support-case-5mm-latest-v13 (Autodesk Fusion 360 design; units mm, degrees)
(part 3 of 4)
offset_faces "OffsetFaces9" distance -0.2
offset_faces "OffsetFaces10" distance -0.2
sketch "Sketch42" plane through (87.9, 0, 0) normal (-1, 0, 0) x axis (0, -1, 0)
  line L1 (-42.6941, 1.4134) -> (-39.025, 1.4134)
  line L2 (-39.025, 5.5134) -> (-42.6941, 5.5134)
  line L3 (-36.6258, -0.6871) -> (-36.1258, 0.3129)
  line L4 (-36.8742, 0.6871) -> (-37.3742, -0.3129)
  line L5 (-42.0276, 9.5417) -> (-40.8255, 7.1376)
  line L6 (-38.6336, 8.2336) -> (-39.8356, 10.6377)
  line L7 (-44.3847, -0.2206) -> (-43.6433, -1.2821)
  line L8 (-42.503, -0.4857) -> (-43.2444, 0.5758)
  line L9 (-39.809, -1.2436) -> (-38.3992, -0.0011)
  line L10 (-39.1812, 0.8862) -> (-40.591, -0.3564)
  line L11 (-32.6474, 3.0718) -> (-31.5271, 3.9384)
  line L12 (-32.7999, 5.5837) -> (-33.9202, 4.7171)
  line L13 (-47.0891, -0.5864) -> (-45.9587, 2.459)
  line L14 (-47.497, 3.03) -> (-48.6275, -0.0154)
  curve K1 (-49.7958, -1.519) -> (-53.502, -1.4707)
  line L15 (-34.6, -1.519) -> (-42.7898, -1.519)
  line L16 (-34.6, 0.4) -> (-34.6, -1.519)
  line L17 (-20.9875, 1.4) -> (-33.6, 1.4)
  line L18 (-19.9875, -1.519) -> (-19.9875, 0.4)
  line L19 (-6.2042, -1.519) -> (-19.9875, -1.519)
  curve K2 (-2.4862, -1.4711) -> (-6.2042, -1.519)
  line L20 (-2.4862, 23.1) -> (-2.4862, -1.4711)
  line L21 (-14.0576, 23.1) -> (-2.4862, 23.1)
  line L22 (-39.9941, 21.6) -> (-15.9941, 21.6)
  line L23 (-53.502, 23.1) -> (-41.9306, 23.1)
  line L24 (-53.502, -1.4707) -> (-53.502, 23.1)
  line L25 (-34.7657, 6.2918) -> (-37.5941, 3.4634)
  line L26 (-33.5941, 3.4634) -> (-37.5941, 3.4634)
  line L27 (-45.169, 0.9885) -> (-42.6941, 3.4634)
  line L28 (-39.1941, 3.4634) -> (-42.6941, 3.4634)
  line L29 (-45.169, 2.0492) -> (-43.7548, 3.4634)
  line L30 (-42.6941, 2.4027) -> (-44.1083, 0.9885)
  line L31 (-45.169, 0.9885) -> (-42.6941, 3.4634)
  line L32 (-34.7657, 5.2312) -> (-36.5335, 3.4634)
  line L33 (-37.5941, 4.5241) -> (-35.8264, 6.2918)
  line L34 (-34.7657, 6.2918) -> (-37.5941, 3.4634)
  line L35 (-43.3565, -1.519) -> (-49.7958, -1.519)
  arc A1 centre (-37.5941, 3.4634) radius 2.5 clockwise from (-39.025, 5.5134) to (-39.025, 1.4134)
  arc A2 centre (-42.6941, 3.4634) radius 2.05 clockwise from (-42.6941, 1.4134) to (-42.6941, 5.5134)
  arc A3 centre (-37, -0.5) radius 0.4184 clockwise from (-36.6258, -0.6871) to (-37.3742, -0.3129)
  arc A4 centre (-36.5, 0.5) radius 0.4184 clockwise from (-36.8742, 0.6871) to (-36.1258, 0.3129)
  arc A5 centre (-40.9316, 10.0897) radius 1.2254 clockwise from (-42.0276, 9.5417) to (-39.8356, 10.6377)
  arc A6 centre (-39.7296, 7.6856) radius 1.2254 clockwise from (-38.6336, 8.2336) to (-40.8255, 7.1376)
  arc A7 centre (-43.8145, 0.1776) radius 0.6955 clockwise from (-44.3847, -0.2206) to (-43.2444, 0.5758)
  arc A8 centre (-43.0731, -0.8839) radius 0.6955 clockwise from (-42.503, -0.4857) to (-42.7898, -1.519)
  arc A9 centre (-40.2, -0.8) radius 0.5914 clockwise from (-39.809, -1.2436) to (-40.591, -0.3564)
  arc A10 centre (-38.7902, 0.4426) radius 0.5914 clockwise from (-39.1812, 0.8862) to (-38.3992, -0.0011)
  arc A11 centre (-33.2838, 3.8945) radius 1.0401 clockwise from (-32.6474, 3.0718) to (-33.9202, 4.7171)
  arc A12 centre (-32.1635, 4.7611) radius 1.0401 clockwise from (-32.7999, 5.5837) to (-31.5271, 3.9384)
  arc A13 centre (-47.8583, -0.3009) radius 0.8205 clockwise from (-47.0891, -0.5864) to (-48.6275, -0.0154)
  arc A14 centre (-46.7279, 2.7445) radius 0.8205 clockwise from (-47.497, 3.03) to (-45.9587, 2.459)
  arc A15 centre (-33.6, 0.4) radius 1 clockwise from (-34.6, 0.4) to (-33.6, 1.4)
  arc A16 centre (-20.9875, 0.4) radius 1 clockwise from (-20.9875, 1.4) to (-19.9875, 0.4)
  arc A17 centre (-14.0576, 22.6) radius 0.5 clockwise from (-14.5418, 22.725) to (-14.0576, 23.1)
  arc A18 centre (-15.9941, 23.1) radius 1.5 clockwise from (-14.5418, 22.725) to (-15.9941, 21.6)
  arc A19 centre (-39.9941, 23.1) radius 1.5 clockwise from (-39.9941, 21.6) to (-41.4465, 22.725)
  arc A20 centre (-41.9306, 22.6) radius 0.5 clockwise from (-41.9306, 23.1) to (-41.4465, 22.725)
  arc A21 centre (-44.6387, 1.5188) radius 0.75 clockwise from (-44.1083, 0.9885) to (-45.169, 2.0492)
  arc A22 centre (-43.2245, 2.9331) radius 0.75 clockwise from (-43.7548, 3.4634) to (-42.6941, 2.4027)
  arc A23 centre (-35.296, 5.7615) radius 0.75 clockwise from (-35.8264, 6.2918) to (-34.7657, 5.2312)
  arc A24 centre (-37.0638, 3.9937) radius 0.75 clockwise from (-36.5335, 3.4634) to (-37.5941, 4.5241)
  arc A25 centre (-43.0731, -0.8839) radius 0.6955 clockwise from (-43.3565, -1.519) to (-43.6433, -1.2821)
  point P4 (-37.5941, 3.4634)
  point P70 (-37.5941, 3.4634)
  point P7 (-42.6941, 3.4634)
  point P73 (-42.6941, 3.4634)
  point P82 (-42.6941, 3.4634)
  point P74 (-45.169, 0.9885)
  point P89 (-37.5941, 3.4634)
  point P71 (-34.7657, 6.2918)
  horizontal L26
  coincident P4 P70
  horizontal L28
  coincident P7 P73
  tangent L29 A21
  tangent A21 L30
  parallel L29 L30
  tangent L30 A22
  tangent L29 A22
  midpoint A22 P82
  midpoint P74 A21
  parallel L27 L31
  coincident P7 P82
  tangent L32 A23
  tangent A23 L33
  parallel L32 L33
  tangent L33 A24
  tangent L32 A24
  midpoint A24 P89
  midpoint P71 A23
  parallel L25 L34
  coincident P4 P89
  dimension "d352" distance P70 P71 = 4
  dimension "d353" angle L25 L26 = 45
  dimension "d354" angle L27 L28 = 135
  dimension "d355" distance P73 P74 = 3.5
  dimension "d356" diameter A21 = 1.5
  dimension "d357" diameter A23 = 1.5
extrude "Extrude56" cut sketch "Sketch42" profile of A1 A2 L25 L27 L29 A21 L30 L32 A23 L33 against normal blind 2
extrude "Extrude57" add sketch "Sketch42" profile of A1 A2 L25 L27 L29 A21 L30 A22 L32 A23 L33 A24 against normal blind 2
sketch "Sketch43" plane through (90.7, 0, 0) normal (1, 0, 0) x axis (0, 1, 0)
  line L1 (37.5941, 5.3134) -> (41.9463, 5.3134)
  line L2 (41.9463, 1.6134) -> (37.5941, 1.6134)
  line L3 (43.7963, 3.4634) -> (35.7441, 3.4634)
  line L4 (40, 4.9702) -> (40, 3.6932)
  line L5 (39.5405, 3.6932) -> (39.5405, 4.9702)
  line L6 (39.7702, 5.2) -> (39.7702, 3.4634)
  line L7 (39.2702, 4.9702) -> (39.7702, 4.9702)
  line L8 (40.2702, 4.9702) -> (39.7702, 4.9702)
  line L9 (39.2702, 4.3294) -> (39.2702, 4.9702)
  line L10 (40.2702, 4.3294) -> (40.2702, 4.9702)
  arc A1 centre (41.9463, 3.4634) radius 1.85 clockwise from (41.9463, 5.3134) to (41.9463, 1.6134)
  arc A2 centre (37.5941, 3.4634) radius 1.85 clockwise from (37.5941, 1.6134) to (37.5941, 5.3134)
  circle C1 centre (39.7702, 3.4634) radius 1
  circle C2 centre (39.7702, 3.4634) radius 1.5
  arc A3 centre (39.7702, 4.9702) radius 0.2298 clockwise from (39.5405, 4.9702) to (40, 4.9702)
  arc A4 centre (39.7702, 3.6932) radius 0.2298 clockwise from (40, 3.6932) to (39.5405, 3.6932)
  point P8 (35.7441, 3.4634)
  point P9 (43.7963, 3.4634)
  point P10 (39.7702, 3.4634)
  point P18 (39.7702, 3.4634)
  point P19 (39.7702, 5.2)
  point P17 (39.7702, 4.9702)
  point P20 (39.7702, 4.9702)
  point P22 (39.7702, 4.9702)
  point P24 (39.2702, 4.3294)
  point P25 (40.2702, 4.3294)
  point P21 (39.2702, 4.9702)
  point P23 (40.2702, 4.9702)
  midpoint A2 P8
  midpoint A1 P9
  midpoint L3 P10
  tangent L4 A3
  tangent A3 L5
  parallel L4 L5
  tangent L5 A4
  tangent L4 A4
  midpoint A4 P18
  midpoint A3 P19
  perpendicular L3 L6
  coincident P10 P18
  coincident P17 P20
  perpendicular L6 L7
  coincident P17 P22
  perpendicular L6 L8
  coincident C1 P24
  perpendicular L7 L9
  coincident C1 P25
  perpendicular L8 L10
  dimension "d362" diameter C1 = 2
  dimension "d363" = 0.5
  dimension "d364" distance P20 P21 = 0.5
  dimension "d365" distance P22 P23 = 0.5
extrude "Extrude58" cut sketch "Sketch43" profile of L3 C1 C2 L4 A3 L5 A4 L7 L8 L9 L10 against normal blind 0.5
offset_faces "OffsetFaces11" distance -0.1
offset_faces "OffsetFaces12" distance -0.1
extrude "Extrude59" add of existing geometry blind 0.5
delete_face "DeleteFace75"
delete_face "DeleteFace76"
offset_faces "OffsetFaces13" distance 0.1
move_face "MoveFace6"
move_face "MoveFace7"
move_face "MoveFace8"
extrude "Extrude60" add of existing geometry blind 3.9 second side blind -0.2
split "Split1"
extrude "Extrude61" cut of existing geometry blind -0.4
sketch "Sketch44" plane through (0, 0, 1.6134) normal (0, 0, -1) x axis (1, 0, 0)
  line L1 (89.669, -41.4517) -> (90.45, -41.4517)
  line L2 (90.45, -41.9517) -> (89.669, -41.9517)
  line L3 (89.419, -41.7017) -> (90.7, -41.7017)
  line L4 (89.75, -37.5941) -> (90.45, -37.5941)
  line L5 (90.45, -38.0941) -> (89.75, -38.0941)
  line L6 (89.5, -37.8441) -> (90.7, -37.8441)
  line L7 (89.75, -38.9116) -> (90.45, -38.9116)
  line L8 (90.45, -39.4116) -> (89.75, -39.4116)
  line L9 (89.5, -39.1616) -> (90.7, -39.1616)
  line L10 (89.75, -40.3058) -> (90.45, -40.3058)
  line L11 (90.45, -40.8058) -> (89.75, -40.8058)
  line L12 (89.5, -40.5558) -> (90.7, -40.5558)
  line L13 (88.0999, -42.1845) -> (88.9142, -42.1845)
  line L14 (88.9142, -42.6845) -> (88.0999, -42.6845)
  line L15 (87.8499, -42.4345) -> (89.1642, -42.4345)
  line L16 (88.0672, -39.0366) -> (88.9256, -39.0366)
  line L17 (88.9256, -39.5366) -> (88.0672, -39.5366)
  line L18 (87.8172, -39.2866) -> (89.1756, -39.2866)
  line L19 (88.0572, -41.3428) -> (88.9428, -41.3428)
  line L20 (88.9428, -41.8428) -> (88.0572, -41.8428)
  line L21 (87.8072, -41.5928) -> (89.1928, -41.5928)
  line L22 (88.0771, -40.3229) -> (88.9229, -40.3229)
  line L23 (88.9229, -40.8229) -> (88.0771, -40.8229)
  line L24 (87.8271, -40.5729) -> (89.1729, -40.5729)
  line L25 (89.5, -41.9463) -> (89.5, -37.5941)
  line L26 (90.7, -37.5941) -> (90.7, -41.9463)
  line L27 (90.7, -41.9463) -> (89.5, -41.9463)
  line L28 (89.5, -37.5941) -> (90.7, -37.5941)
  arc A1 centre (89.669, -41.7017) radius 0.25 clockwise from (89.669, -41.9517) to (89.669, -41.4517)
  arc A2 centre (90.45, -41.7017) radius 0.25 clockwise from (90.45, -41.4517) to (90.45, -41.9517)
  arc A3 centre (89.75, -37.8441) radius 0.25 clockwise from (89.75, -38.0941) to (89.75, -37.5941)
  arc A4 centre (90.45, -37.8441) radius 0.25 clockwise from (90.45, -37.5941) to (90.45, -38.0941)
  arc A5 centre (89.75, -39.1616) radius 0.25 clockwise from (89.75, -39.4116) to (89.75, -38.9116)
  arc A6 centre (90.45, -39.1616) radius 0.25 clockwise from (90.45, -38.9116) to (90.45, -39.4116)
  arc A7 centre (89.75, -40.5558) radius 0.25 clockwise from (89.75, -40.8058) to (89.75, -40.3058)
  arc A8 centre (90.45, -40.5558) radius 0.25 clockwise from (90.45, -40.3058) to (90.45, -40.8058)
  arc A9 centre (88.0999, -42.4345) radius 0.25 clockwise from (88.0999, -42.6845) to (88.0999, -42.1845)
  arc A10 centre (88.9142, -42.4345) radius 0.25 clockwise from (88.9142, -42.1845) to (88.9142, -42.6845)
  arc A11 centre (88.0672, -39.2866) radius 0.25 clockwise from (88.0672, -39.5366) to (88.0672, -39.0366)
  arc A12 centre (88.9256, -39.2866) radius 0.25 clockwise from (88.9256, -39.0366) to (88.9256, -39.5366)
  arc A13 centre (88.0572, -41.5928) radius 0.25 clockwise from (88.0572, -41.8428) to (88.0572, -41.3428)
  arc A14 centre (88.9428, -41.5928) radius 0.25 clockwise from (88.9428, -41.3428) to (88.9428, -41.8428)
  arc A15 centre (88.0771, -40.5729) radius 0.25 clockwise from (88.0771, -40.8229) to (88.0771, -40.3229)
  arc A16 centre (88.9229, -40.5729) radius 0.25 clockwise from (88.9229, -40.3229) to (88.9229, -40.8229)
  point P8 (90.7, -41.7017)
  point P9 (89.419, -41.7017)
  point P16 (90.7, -37.8441)
  point P17 (89.5, -37.8441)
  point P24 (90.7, -39.1616)
  point P25 (89.5, -39.1616)
  point P32 (90.7, -40.5558)
  point P33 (89.5, -40.5558)
  point P40 (89.1642, -42.4345)
  point P41 (87.8499, -42.4345)
  point P48 (89.1756, -39.2866)
  point P49 (87.8172, -39.2866)
  point P56 (89.1928, -41.5928)
  point P57 (87.8072, -41.5928)
  point P64 (89.1729, -40.5729)
  point P65 (87.8271, -40.5729)
  tangent L1 A1
  tangent A1 L2
  parallel L1 L2
  tangent L2 A2
  tangent L1 A2
  midpoint A2 P8
  midpoint A1 P9
  tangent L4 A3
  tangent A3 L5
  parallel L4 L5
  tangent L5 A4
  tangent L4 A4
  midpoint A4 P16
  midpoint A3 P17
  tangent L7 A5
  tangent A5 L8
  parallel L7 L8
  tangent L8 A6
  tangent L7 A6
  midpoint A6 P24
  midpoint A5 P25
  tangent L10 A7
  tangent A7 L11
  parallel L10 L11
  tangent L11 A8
  tangent L10 A8
  midpoint A8 P32
  midpoint A7 P33
  tangent L13 A9
  tangent A9 L14
  parallel L13 L14
  tangent L14 A10
  tangent L13 A10
  midpoint A10 P40
  midpoint A9 P41
  horizontal L15
  tangent L16 A11
  tangent A11 L17
  parallel L16 L17
  tangent L17 A12
  tangent L16 A12
  midpoint A12 P48
  midpoint A11 P49
  horizontal L18
  tangent L19 A13
  tangent A13 L20
  parallel L19 L20
  tangent L20 A14
  tangent L19 A14
  midpoint A14 P56
  midpoint A13 P57
  horizontal L21
  tangent L22 A15
  tangent A15 L23
  parallel L22 L23
  tangent L23 A16
  tangent L22 A16
  midpoint A16 P64
  midpoint A15 P65
  horizontal L24
  dimension "d405" distance L7 L8 = 0.5
  dimension "d406" distance L4 L5 = 0.5
  dimension "d407" distance L10 L11 = 0.5
  dimension "d408" distance L1 L2 = 0.5
  dimension "d409" distance L13 L14 = 0.5
  dimension "d410" distance L19 L20 = 0.5
  dimension "d411" distance L22 L23 = 0.5
  dimension "d412" distance L16 L17 = 0.5
extrude "Extrude62" add sketch "Sketch44" profile of L1 A1 L2 A2 L4 A3 L5 A4 L7 A5 L8 A6 L10 A7 L11 A8 L13 A9 L14 A10 L16 A11 L17 A12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 along normal blind 0.2
sketch "Sketch45" plane through (0, 41.9517, 0) normal (0, 1, 0) x axis (-1, 0, 0)
  line L1 (-89.9364, 1.4134) -> (-89.9364, 5.3134)
  line L2 (-90.2657, 1.4134) -> (-89.9364, 1.4134)
  line L3 (-90.2657, 5.3134) -> (-90.2657, 1.4134)
  line L4 (-90.2657, 4.3984) -> (-89.9364, 4.3984)
  line L5 (-90.7, 5.3134) -> (-89.5, 5.3134)
  line L6 (-89.5, 5.3134) -> (-89.5, 1.6134)
  line L7 (-90.5016, 1.6134) -> (-90.7, 1.6134)
  line L8 (-89.6174, 1.6134) -> (-90.5016, 1.6134)
  line L9 (-90.7, 1.6134) -> (-90.7, 5.3134)
  line L10 (-89.5, 1.6134) -> (-89.6174, 1.6134)
  point P6 (-89.9364, 4.3984)
  point P7 (-90.2657, 4.3984)
  vertical L1
  horizontal L2
  vertical L3
  coincident L1 P6
  coincident L3 P7
  perpendicular L3 L4
extrude "Extrude63" cut sketch "Sketch45" profile of L1 L2 L3 L4 against normal blind 4.353
sketch "Sketch46" plane through (0, 42.6941, 0) normal (0, 1, 0) x axis (-1, 0, 0)
  line L1 (-89.1, 1.6134) -> (-89.1, 5.3134)
  line L2 (-87.9, 1.6134) -> (-89.1, 1.6134)
  line L3 (-87.9, 5.3134) -> (-87.9, 1.6134)
  line L4 (-89.1, 5.3134) -> (-87.9, 5.3134)
  line L5 (-88.3, 5.3134) -> (-88.7263, 5.3134)
  line L6 (-88.3, 1.4) -> (-88.3, 5.3134)
  line L7 (-88.7263, 1.4) -> (-88.3, 1.4)
  line L8 (-88.7263, 5.3134) -> (-88.7263, 1.4)
  line L9 (-88.3, 4.4724) -> (-88.7263, 4.4724)
  point P6 (-88.7263, 5.3134)
  point P10 (-88.7263, 4.4724)
  point P11 (-88.3, 4.4724)
  horizontal L5
  vertical L6
  horizontal L7
  vertical L8
  coincident L4 P6
  coincident L8 P10
  coincident L6 P11
  perpendicular L6 L9
extrude "Extrude64" cut sketch "Sketch46" profile of L2 L6 L8 L9 against normal blind 3.7
extrude "Extrude65" cut of existing geometry blind -0.2
delete_face "DeleteFace77"
delete_face "DeleteFace78"
delete_face "DeleteFace79"
sketch "Sketch52" plane through (0, 0, -1.519) normal (0, 0, 1) x axis (-1, 0, 0)
  curve K1 (-9.9047, -21.9534) -> (-9.8441, -21.9301)
  line L1 (-10.1191, -21.9534) -> (-9.9047, -21.9534)
  curve K2 (-10.8368, -21.6668) -> (-10.1191, -21.9534)
  curve K3 (-11.1351, -20.9794) -> (-10.8368, -21.6668)
  curve K4 (-10.8368, -20.2919) -> (-11.1351, -20.9794)
  curve K5 (-10.1191, -20.0053) -> (-10.8368, -20.2919)
  line L2 (-9.9187, -20.0053) -> (-10.1191, -20.0053)
  curve K6 (-9.8605, -20.0286) -> (-9.9187, -20.0053)
  curve K7 (-9.8348, -20.0892) -> (-9.8605, -20.0286)
  line L3 (-9.8348, -20.4947) -> (-9.8348, -20.0892)
  curve K8 (-9.8908, -20.5506) -> (-9.8348, -20.4947)
  line L4 (-10.1191, -20.5506) -> (-9.8908, -20.5506)
  curve K9 (-10.4547, -20.6764) -> (-10.1191, -20.5506)
  curve K10 (-10.5945, -20.9794) -> (-10.4547, -20.6764)
  curve K11 (-10.4547, -21.2776) -> (-10.5945, -20.9794)
  curve K12 (-10.1191, -21.4035) -> (-10.4547, -21.2776)
  line L5 (-9.8768, -21.4035) -> (-10.1191, -21.4035)
  curve K13 (-9.8208, -21.4641) -> (-9.8768, -21.4035)
  line L6 (-9.8208, -21.8695) -> (-9.8208, -21.4641)
  curve K14 (-9.8441, -21.9301) -> (-9.8208, -21.8695)
  curve K15 (-14.5107, -18.5559) -> (-14.5176, -18.6305)
  curve K16 (-14.4384, -18.5186) -> (-14.5107, -18.5559)
  line L7 (-13.9957, -18.5186) -> (-14.4384, -18.5186)
  curve K17 (-13.9491, -18.5466) -> (-13.9957, -18.5186)
  line L8 (-13.2919, -20.2011) -> (-13.9491, -18.5466)
  curve K18 (-13.2873, -20.243) -> (-13.2919, -20.2011)
  line L9 (-13.2873, -20.6764) -> (-13.2873, -20.243)
  curve K19 (-13.3432, -20.7324) -> (-13.2873, -20.6764)
  line L10 (-13.4504, -20.7324) -> (-13.3432, -20.7324)
  curve K20 (-13.7953, -20.8256) -> (-13.4504, -20.7324)
  curve K21 (-13.9304, -21.0866) -> (-13.7953, -20.8256)
  curve K22 (-13.7929, -21.3615) -> (-13.9304, -21.0866)
  curve K23 (-13.4504, -21.4641) -> (-13.7929, -21.3615)
  line L11 (-13.2127, -21.4641) -> (-13.4504, -21.4641)
  curve K24 (-13.1521, -21.5246) -> (-13.2127, -21.4641)
  line L12 (-13.1521, -21.9254) -> (-13.1521, -21.5246)
  curve K25 (-13.1778, -21.9884) -> (-13.1521, -21.9254)
  curve K26 (-13.2407, -22.014) -> (-13.1778, -21.9884)
  line L13 (-13.4504, -22.014) -> (-13.2407, -22.014)
  curve K27 (-14.1751, -21.7483) -> (-13.4504, -22.014)
  curve K28 (-14.471, -21.0866) -> (-14.1751, -21.7483)
  curve K29 (-14.3196, -20.5972) -> (-14.471, -21.0866)
  curve K30 (-13.9164, -20.2756) -> (-14.3196, -20.5972)
  curve K31 (-13.8838, -20.2011) -> (-13.9164, -20.2756)
  line L14 (-14.5176, -18.6305) -> (-13.8838, -20.2011)
  curve K32 (-16.8926, -18.5979) -> (-16.9159, -18.5373)
  line L15 (-16.8926, -20.3036) -> (-16.8926, -18.5979)
  curve K33 (-16.9136, -20.3409) -> (-16.8926, -20.3036)
  curve K34 (-16.9579, -20.3455) -> (-16.9136, -20.3409)
  curve K35 (-17.3354, -19.9611) -> (-16.9579, -20.3455)
  curve K36 (-17.4938, -19.3482) -> (-17.3354, -19.9611)
  line L16 (-17.4938, -18.5979) -> (-17.4938, -19.3482)
  curve K37 (-17.4682, -18.5373) -> (-17.4938, -18.5979)
  curve K38 (-17.4099, -18.514) -> (-17.4682, -18.5373)
  line L17 (-16.9765, -18.514) -> (-17.4099, -18.514)
  curve K39 (-16.9159, -18.5373) -> (-16.9765, -18.514)
  curve K40 (-16.8926, -21.0633) -> (-16.9229, -20.984)
  line L18 (-16.8926, -21.8835) -> (-16.8926, -21.0633)
  curve K41 (-16.9299, -21.9674) -> (-16.8926, -21.8835)
  curve K42 (-17.0138, -21.9953) -> (-16.9299, -21.9674)
  line L19 (-17.4332, -21.9674) -> (-17.0138, -21.9953)
  curve K43 (-17.5824, -21.8695) -> (-17.4332, -21.9674)
  curve K44 (-18.6869, -19.8096) -> (-17.5824, -21.8695)
  curve K45 (-19.1623, -19.4834) -> (-18.6869, -19.8096)
  line L20 (-19.2741, -19.4834) -> (-19.1623, -19.4834)
  curve K46 (-19.344, -19.4135) -> (-19.2741, -19.4834)
  line L21 (-19.344, -18.5839) -> (-19.344, -19.4135)
  curve K47 (-19.323, -18.535) -> (-19.344, -18.5839)
  curve K48 (-19.2741, -18.514) -> (-19.323, -18.535)
  line L22 (-18.8453, -18.514) -> (-19.2741, -18.514)
  curve K49 (-18.6915, -18.6072) -> (-18.8453, -18.514)
  curve K50 (-18.3513, -19.2387) -> (-18.6915, -18.6072)
  curve K51 (-17.8666, -20.1405) -> (-18.3513, -19.2387)
  curve K52 (-17.601, -20.6298) -> (-17.8666, -20.1405)
  curve K53 (-17.4216, -20.8465) -> (-17.601, -20.6298)
  curve K54 (-17.1909, -20.9281) -> (-17.4216, -20.8465)
  curve K55 (-17.1186, -20.9351) -> (-17.1909, -20.9281)
  curve K56 (-17.0487, -20.9421) -> (-17.1186, -20.9351)
  curve K57 (-16.9998, -20.9467) -> (-17.0487, -20.9421)
  curve K58 (-16.9229, -20.984) -> (-16.9998, -20.9467)
  curve K59 (-22.7825, -21.9348) -> (-22.7615, -21.9884)
  line L23 (-22.7825, -21.478) -> (-22.7825, -21.9348)
  curve K60 (-22.7615, -21.4291) -> (-22.7825, -21.478)
  curve K61 (-22.7126, -21.4081) -> (-22.7615, -21.4291)
  line L24 (-20.2985, -21.4081) -> (-22.7126, -21.4081)
  curve K62 (-20.2286, -21.478) -> (-20.2985, -21.4081)
  line L25 (-20.2286, -21.9348) -> (-20.2286, -21.478)
  curve K63 (-20.2985, -22.0093) -> (-20.2286, -21.9348)
  line L26 (-22.7126, -22.0093) -> (-20.2985, -22.0093)
  curve K64 (-22.7615, -21.9884) -> (-22.7126, -22.0093)
  line L27 (-24.5665, -21.9534) -> (-24.4081, -21.3196)
  curve K65 (-24.6504, -22.014) -> (-24.5665, -21.9534)
  line L28 (-25.1211, -22.014) -> (-24.6504, -22.014)
  curve K66 (-25.2003, -21.9534) -> (-25.1211, -22.014)
  line L29 (-26.0998, -18.6212) -> (-25.2003, -21.9534)
  curve K67 (-26.0858, -18.5466) -> (-26.0998, -18.6212)
  curve K68 (-26.0206, -18.514) -> (-26.0858, -18.5466)
  line L30 (-25.5918, -18.514) -> (-26.0206, -18.514)
  curve K69 (-25.5126, -18.5746) -> (-25.5918, -18.514)
  line L31 (-24.8461, -20.9887) -> (-25.5126, -18.5746)
  curve K70 (-24.7436, -21.1052) -> (-24.8461, -20.9887)
  line L32 (-24.4547, -21.2217) -> (-24.7436, -21.1052)
  curve K71 (-24.4081, -21.3196) -> (-24.4547, -21.2217)
  curve K72 (-28.3033, -21.4734) -> (-28.3732, -21.3895)
  line L33 (-28.3033, -21.8835) -> (-28.3033, -21.4734)
  curve K73 (-28.3312, -21.9464) -> (-28.3033, -21.8835)
  curve K74 (-28.3965, -21.9674) -> (-28.3312, -21.9464)
  curve K75 (-29.1049, -21.6388) -> (-28.3965, -21.9674)
  curve K76 (-29.4031, -20.97) -> (-29.1049, -21.6388)
  curve K77 (-29.1002, -20.271) -> (-29.4031, -20.97)
  curve K78 (-29.0699, -20.2011) -> (-29.1002, -20.271)
  curve K79 (-29.1049, -20.1358) -> (-29.0699, -20.2011)
  curve K80 (-29.4031, -19.474) -> (-29.1049, -20.1358)
  curve K81 (-29.3239, -19.0639) -> (-29.4031, -19.474)
  curve K82 (-29.1352, -18.789) -> (-29.3239, -19.0639)
  curve K83 (-28.8765, -18.6258) -> (-29.1352, -18.789)
  curve K84 (-28.6248, -18.5419) -> (-28.8765, -18.6258)
  curve K85 (-28.4198, -18.514) -> (-28.6248, -18.5419)
  curve K86 (-28.3545, -18.535) -> (-28.4198, -18.514)
  curve K87 (-28.3266, -18.5979) -> (-28.3545, -18.535)
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  point P1481 (-20.1586, -3.5211)
  point P1493 (-20.1586, -3.5211)
  point P1467 (-78.15, -52.5)
  point P1497 (-78.15, -52.5)
  point P1502 (-25.4086, -9.5211)
  point P1503 (-25.4086, -9.5211)
  point P1500 (-83.4, -46.5)
  point P1504 (-83.4, -46.5)
  point P1495 (-20.1586, -3.5211)
  point P1496 (-30.6586, -3.5211)
  point P1498 (-88.65, -52.5)
  point P1499 (-83.4, -52.5)
  point P1501 (-25.4086, -3.5211)
  coincident P1481 P1493
  coincident P1467 P1497
  coincident P1502 P1503
  coincident P1500 P1504
  dimension "d483" distance P1495 P1496 = 10.5
  dimension "d484" distance P1497 P1498 = 10.5
  dimension "d485" distance P1499 P1500 = 6
  dimension "d486" distance P1501 P1502 = 6
  dimension "d487" diameter = 4
  dimension "d488" diameter = 4
extrude "Extrude95" cut sketch "Sketch52" against normal blind 1.4
extrude "Extrude96" cut of existing geometry blind 18
fillet "Fillet35" radius 1.5
extrude "Extrude67" cut of existing geometry blind -0.35
extrude "Extrude68" add of existing geometry blind 0.1
extrude "Extrude69" add of existing geometry blind 0.1
extrude "Extrude70" add of existing geometry blind 0.1
extrude "Extrude71" cut of existing geometry blind 3.059
extrude "Extrude72" add of existing geometry blind 0.5
extrude "Extrude73" add of existing geometry blind 0.3
extrude "Extrude74" cut of existing geometry blind -0.2
sketch "Sketch48" plane through (90.7, 0, 0) normal (1, 0, 0) x axis (0, 1, 0)
  line L1 (33.6, 2.4) -> (20.9875, 2.4)
  line L2 (35.6, -2.019) -> (35.6, 0.4)
  line L3 (53.302, -2.019) -> (35.6, -2.019)
  line L4 (53.302, 21.6) -> (53.302, -2.019)
  line L5 (2.6862, 21.6) -> (53.302, 21.6)
  line L6 (2.6862, -2.019) -> (2.6862, 21.6)
  line L7 (18.9875, -2.019) -> (2.6862, -2.019)
  line L8 (18.9875, 0.4) -> (18.9875, -2.019)
  line L9 (45.9587, 2.459) -> (47.0891, -0.5864)
  line L10 (48.6275, -0.0154) -> (47.497, 3.03)
  line L11 (31.5271, 3.9384) -> (32.6474, 3.0718)
  line L12 (33.9202, 4.7171) -> (32.7999, 5.5837)
  line L13 (38.9459, -0.0641) -> (40.3557, -1.3067)
  line L14 (41.0054, -0.5695) -> (39.5957, 0.6731)
  line L15 (43.2799, -1.2004) -> (44.0213, -0.1389)
  line L16 (42.8809, 0.6575) -> (42.1396, -0.404)
  line L17 (40.8255, 7.1376) -> (42.0276, 9.5417)
  line L18 (39.8356, 10.6377) -> (38.6336, 8.2336)
  line L19 (36.0308, 0.0283) -> (36.5308, -0.9717)
  line L20 (37.2792, -0.5974) -> (36.7792, 0.4026)
  line L21 (12.2696, 11.1784) -> (10.1957, 6.7344)
  line L22 (8.1961, 7.6675) -> (10.27, 12.1116)
  line L23 (11.2698, 11.645) -> (9.1959, 7.2009)
  line L24 (7.8962, 1.0974) -> (5.2352, 4.3514)
  line L25 (7.4428, 6.1566) -> (10.1038, 2.9026)
  line L26 (9, 2) -> (6.339, 5.254)
  line L27 (13.4999, 13.3063) -> (10.5022, 15.3315)
  line L28 (11.9632, 17.4942) -> (14.961, 15.469)
  line L29 (14.2304, 14.3876) -> (11.2327, 16.4128)
  line L30 (12.5091, 6.5466) -> (11.9217, 7.6354)
  line L31 (12.6176, 8.0108) -> (13.205, 6.9221)
  line L32 (12.857, 6.7344) -> (12.2696, 7.8231)
  line L33 (41.7017, 1.4134) -> (41.9463, 1.4134)
  line L34 (41.9463, 5.5134) -> (37.5941, 5.5134)
  line L35 (40.5558, 1.4134) -> (41.7017, 1.4134)
  line L36 (39.1616, 1.4134) -> (40.5558, 1.4134)
  line L37 (37.8441, 1.4134) -> (39.1616, 1.4134)
  line L38 (37.5941, 1.4134) -> (37.8441, 1.4134)
  arc A1 centre (33.6, 0.4) radius 2 clockwise from (33.6, 2.4) to (35.6, 0.4)
  arc A2 centre (20.9875, 0.4) radius 2 clockwise from (18.9875, 0.4) to (20.9875, 2.4)
  arc A3 centre (46.7279, 2.7445) radius 0.8205 clockwise from (45.9587, 2.459) to (47.497, 3.03)
  arc A4 centre (47.8583, -0.3009) radius 0.8205 clockwise from (48.6275, -0.0154) to (47.0891, -0.5864)
  arc A5 centre (32.1635, 4.7611) radius 1.0401 clockwise from (31.5271, 3.9384) to (32.7999, 5.5837)
  arc A6 centre (33.2838, 3.8945) radius 1.0401 clockwise from (33.9202, 4.7171) to (32.6474, 3.0718)
  arc A7 centre (39.2708, 0.3045) radius 0.4914 clockwise from (38.9459, -0.0641) to (39.5957, 0.6731)
  arc A8 centre (40.6806, -0.9381) radius 0.4914 clockwise from (41.0054, -0.5695) to (40.3557, -1.3067)
  arc A9 centre (42.7097, -0.8022) radius 0.6955 clockwise from (43.2799, -1.2004) to (42.1396, -0.404)
  arc A10 centre (43.4511, 0.2593) radius 0.6955 clockwise from (42.8809, 0.6575) to (44.0213, -0.1389)
  arc A11 centre (39.7296, 7.6856) radius 1.2254 clockwise from (40.8255, 7.1376) to (38.6336, 8.2336)
  arc A12 centre (40.9316, 10.0897) radius 1.2254 clockwise from (39.8356, 10.6377) to (42.0276, 9.5417)
  arc A13 centre (36.405, 0.2154) radius 0.4184 clockwise from (36.0308, 0.0283) to (36.7792, 0.4026)
  arc A14 centre (36.905, -0.7846) radius 0.4184 clockwise from (37.2792, -0.5974) to (36.5308, -0.9717)
  arc A15 centre (11.2698, 11.645) radius 1.1033 clockwise from (10.27, 12.1116) to (12.2696, 11.1784)
  arc A16 centre (9.1959, 7.2009) radius 1.1033 clockwise from (10.1957, 6.7344) to (8.1961, 7.6675)
  arc A17 centre (9, 2) radius 1.4259 clockwise from (10.1038, 2.9026) to (7.8962, 1.0974)
  arc A18 centre (6.339, 5.254) radius 1.4259 clockwise from (5.2352, 4.3514) to (7.4428, 6.1566)
  arc A19 centre (14.2304, 14.3876) radius 1.305 clockwise from (14.961, 15.469) to (13.4999, 13.3063)
  arc A20 centre (11.2327, 16.4128) radius 1.305 clockwise from (10.5022, 15.3315) to (11.9632, 17.4942)
  arc A21 centre (12.857, 6.7344) radius 0.3954 clockwise from (13.205, 6.9221) to (12.5091, 6.5466)
  arc A22 centre (12.2696, 7.8231) radius 0.3954 clockwise from (11.9217, 7.6354) to (12.6176, 8.0108)
  arc A23 centre (41.9463, 3.4634) radius 2.05 clockwise from (41.9463, 5.5134) to (41.9463, 1.4134)
  arc A24 centre (37.5941, 3.4634) radius 2.05 clockwise from (37.5941, 1.4134) to (37.5941, 5.5134)
  tangent L21 A15
  tangent A15 L22
  parallel L21 L22
  tangent L22 A16
  tangent L21 A16
  tangent L24 A17
  tangent A17 L25
  parallel L24 L25
  tangent L25 A18
  tangent L24 A18
  tangent L27 A19
  tangent A19 L28
  parallel L27 L28
  tangent L28 A20
  tangent L27 A20
  tangent L30 A21
  tangent A21 L31
  parallel L30 L31
  tangent L31 A22
  tangent L30 A22
extrude "Extrude75" cut sketch "Sketch48" profile of L21 A15 L22 A16 L24 A17 L25 A18 L27 A19 L28 A20 L30 A21 L31 A22 against normal blind 5.7
offset_faces "OffsetFaces15" distance -0.3
extrude "Extrude79" add of existing geometry blind 4.919 second side blind -0.2 (= "0.00 mm - 0.2 mm")
sketch "Sketch50" plane through (0, 0, 1.4) normal (0, 0, -1) x axis (1, 0, 0)
  line L1 (87.9, -33.6) -> (87.9, -20.9875)
  line L2 (89.7, -33.6) -> (87.9, -33.6)
  line L3 (89.7, -20.9875) -> (89.7, -33.6)
  line L4 (87.9, -20.9875) -> (89.7, -20.9875)
  line L5 (89.6, -33.6) -> (89.7, -33.6)
  line L6 (89.6, -33.5) -> (89.6, -33.6)
  line L7 (89.7, -33.5) -> (89.6, -33.5)
  line L8 (89.7, -33.6) -> (89.7, -33.5)
  point P4 (89.7, -33.6)
  point P6 (89.7, -33.6)
  horizontal L5
  vertical L6
  horizontal L7
  vertical L8
  coincident P4 P6
extrude "Extrude80" add sketch "Sketch50" profile of L2 L3 L5 L6 L7 L8 along normal blind 0.2
extrude "Extrude81" add of existing geometry blind 4.1 (= "4.30 mm - 0.2 mm") second side blind -0.2 (= "0.00 mm - 0.2 mm")
sketch "Sketch51" plane through (0, 0, 2.7) normal (0, 0, -1) x axis (1, 0, 0)
  line L1 (43.95, -58.002) -> (43.95, -57.002)
  line L2 (51.05, -58.002) -> (43.95, -58.002)
  line L3 (51.05, -57.002) -> (51.05, -58.002)
  line L4 (43.95, -57.002) -> (51.05, -57.002)
  line L5 (79.1, -58) -> (80.1, -58)
  line L6 (79.1, -57) -> (79.1, -58)
  line L7 (80.1, -57) -> (79.1, -57)
  line L8 (80.1, -58) -> (80.1, -57)
  line L9 (76.5, -58) -> (77.5, -58)
  line L10 (76.5, -57) -> (76.5, -58)
  line L11 (77.5, -57) -> (76.5, -57)
  line L12 (77.5, -58) -> (77.5, -57)
  line L13 (72.3, -58) -> (71.2, -58)
  line L14 (72.3, -57) -> (72.3, -58)
  line L15 (71.2, -57) -> (72.3, -57)
  line L16 (71.2, -58) -> (71.2, -57)
  line L17 (73.5, -58) -> (74.5379, -58)
  line L18 (73.5, -57) -> (73.5, -58)
  line L19 (74.5379, -57) -> (73.5, -57)
  line L20 (74.5379, -58) -> (74.5379, -57)
  line L21 (63.5, -57) -> (64.4, -57)
  line L22 (63.5, -58) -> (63.5, -57)
  line L23 (64.4, -58) -> (63.5, -58)
  line L24 (64.4, -57) -> (64.4, -58)
  line L25 (61.2, -57) -> (62.2, -57)
  line L26 (61.2, -58) -> (61.2, -57)
  line L27 (62.2, -58) -> (61.2, -58)
  line L28 (62.2, -57) -> (62.2, -58)
  line L29 (58.4, -57) -> (57.4, -57)
  line L30 (58.4, -58) -> (58.4, -57)
  line L31 (57.4, -58) -> (58.4, -58)
  line L32 (57.4, -57) -> (57.4, -58)
  line L33 (59.255, -58) -> (60.1788, -58)
  line L34 (59.255, -57) -> (59.255, -58)
  line L35 (60.1788, -57) -> (59.255, -57)
  line L36 (60.1788, -58) -> (60.1788, -57)
  line L37 (50.1, -58) -> (50.1, -57)
  line L38 (50.1, -57) -> (51, -57)
  line L39 (45, -57) -> (44, -57)
  line L40 (46.7788, -58) -> (46.7788, -57)
  line L41 (44, -57) -> (44, -58)
  line L42 (47.8, -58) -> (47.8, -57)
  line L43 (45, -58) -> (45, -57)
  line L44 (45.855, -58) -> (46.7788, -58)
  line L45 (48.8, -58) -> (47.8, -58)
  line L46 (44, -58) -> (45, -58)
  line L47 (51, -57) -> (51, -58)
  line L48 (46.7788, -57) -> (45.855, -57)
  line L49 (47.8, -57) -> (48.8, -57)
  line L50 (51, -58) -> (50.1, -58)
  line L51 (48.8, -57) -> (48.8, -58)
  line L52 (45.855, -57) -> (45.855, -58)
  horizontal L5
  vertical L6
  horizontal L7
  vertical L8
  horizontal L9
  vertical L10
  horizontal L11
  vertical L12
  horizontal L13
  vertical L14
  horizontal L15
  vertical L16
  horizontal L17
  vertical L18
  horizontal L19
  vertical L20
  horizontal L21
  vertical L22
  horizontal L23
  vertical L24
  horizontal L25
  vertical L26
  horizontal L27
  vertical L28
  horizontal L29
  vertical L30
  horizontal L31
  vertical L32
  horizontal L33
  vertical L34
  horizontal L35
  vertical L36
  horizontal L38
  vertical L37
  horizontal L50
  vertical L47
  horizontal L49
  vertical L42
  horizontal L45
  vertical L51
  horizontal L39
  vertical L43
  horizontal L46
  vertical L41
  horizontal L44
  vertical L52
  horizontal L48
  vertical L40
extrude "Extrude82" add sketch "Sketch51" profile of L4 L5 L6 L7 L8 L9 L10 L11 L12 L13 L14 L15 L16 L17 L18 L19 L20 L21 L22 L23 L24 L25 L26 L27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 along normal blind 0.2
extrude "Extrude83" add of existing geometry blind 0.2
extrude "Extrude84" add of existing geometry blind 0.2
extrude "Extrude85" add of existing geometry blind 0.2
extrude "Extrude86" add of existing geometry blind 0.2
extrude "Extrude87" add of existing geometry blind 0.2
extrude "Extrude88" add of existing geometry blind 0.2
extrude "Extrude89" add of existing geometry blind 0.2
extrude "Extrude90" add of existing geometry blind 0.2
extrude "Extrude91" cut sketch "Sketch34" against normal blind 0.2
sketch "Sketch54" plane through (-0.1, 0, 0) normal (-1, 0, 0) x axis (0, -1, 0)
  line L1 (-1.1222, 18.4973) -> (-1.1222, 3.5)
  curve K1 (-1.1222, 18.4973) -> (-1.7103, 19.6364)
  line L2 (-53.302, 19.9973) -> (-2.6862, 19.9973)
  curve K2 (-54.278, 19.6364) -> (-54.8661, 18.4973)
  line L3 (-54.8661, 3.5) -> (-54.8661, 18.4973)
  curve K3 (-54.8661, 3.5) -> (-54.278, 2.3609)
  line L4 (-2.6862, 2) -> (-53.302, 2)
  curve K4 (-1.7103, 2.3609) -> (-1.1222, 3.5)
  line L5 (-2.6862, 19.9973) -> (-53.302, 19.9973)
  line L6 (-53.3, 19.9973) -> (-2.6862, 19.9973)
  line L7 (-2.6862, 2.4699) -> (-53.3, 2.4699)
  line L8 (-34.6431, 2.4699) -> (-19.1431, 2.4699)
  line L9 (-34.6431, 19.4699) -> (-34.6431, 2.4699)
  line L10 (-19.1431, 19.4699) -> (-34.6431, 19.4699)
  line L11 (-19.1431, 2.4699) -> (-19.1431, 19.4699)
  line L12 (-55.9931, 30) -> (-55.9931, -2)
  line L13 (-1.2431, 2.4699) -> (-16.7431, 2.4699)
  line L14 (-1.2431, 19.4699) -> (-1.2431, 2.4699)
  line L15 (-16.7431, 19.4699) -> (-1.2431, 19.4699)
  line L16 (-16.7431, 2.4699) -> (-16.7431, 19.4699)
  line L17 (-37.2931, 2.4699) -> (-54.2931, 2.4699)
  line L18 (-37.2931, 17.2699) -> (-37.2931, 2.4699)
  line L19 (-54.2931, 17.2699) -> (-37.2931, 17.2699)
  line L20 (-54.2931, 2.4699) -> (-54.2931, 17.2699)
  arc A1 centre (-2.6862, 18.4973) radius 1.5 clockwise from (-2.6862, 19.9973) to (-1.7103, 19.6364)
  arc A2 centre (-53.302, 18.4973) radius 1.5 clockwise from (-54.278, 19.6364) to (-53.302, 19.9973)
  arc A3 centre (-53.302, 3.5) radius 1.5 clockwise from (-53.302, 2) to (-54.278, 2.3609)
  arc A4 centre (-2.6862, 3.5) radius 1.5 clockwise from (-1.7103, 2.3609) to (-2.6862, 2)
  point P7 (-53.302, 19.9973)
  point P19 (-53.302, 19.9973)
  point P5 (-2.6862, 19.9973)
  point P20 (-2.6862, 19.9973)
  point P24 (-19.1431, 2.4699)
  point P29 (-16.7431, 2.4699)
  point P33 (-54.2931, 2.4699)
  point P25 (-34.6431, 2.4699)
  point P27 (-19.1431, 19.4699)
  point P30 (-1.2431, 2.4699)
  point P32 (-16.7431, 19.4699)
  point P34 (-37.2931, 2.4699)
  point P36 (-54.2931, 17.2699)
  coincident P7 P19
  coincident P5 P20
  horizontal L6
  horizontal L7
  horizontal L8
  vertical L9
  horizontal L10
  vertical L11
  coincident L7 P24
  horizontal L13
  vertical L14
  horizontal L15
  vertical L16
  coincident L7 P29
  horizontal L17
  vertical L18
  horizontal L19
  vertical L20
  coincident L7 P33
  dimension "d515" distance P24 P25 = 15.5
  dimension "d516" distance P24 P27 = 17
  dimension "d517" distance L9 L12 = 21.35 (= "29.1 mm - ( 15.5 mm / 2 mm ) * 1 mm")
  dimension "d518" distance P29 P30 = 15.5
  dimension "d519" distance P29 P32 = 17
  dimension "d520" distance L12 L16 = 39.25 (= "47 mm - ( 15.5 mm / 2 mm ) * 1 mm")
  dimension "d521" distance P33 P34 = 17
  dimension "d522" distance P33 P36 = 14.8
  dimension "d523" distance L12 L20 = 1.7 (= "10.2 mm - ( 17 / 2 ) * 1 mm")
delete_face "DeleteFace100"
delete_face "DeleteFace101"
delete_face "DeleteFace102"
delete_face "DeleteFace103"
delete_face "DeleteFace104"
delete_face "DeleteFace105"
delete_face "DeleteFace106"
delete_face "DeleteFace107"
delete_face "DeleteFace108"
delete_face "DeleteFace109"
delete_face "DeleteFace110"
delete_face "DeleteFace111"
delete_face "DeleteFace112"
delete_face "DeleteFace113"
delete_face "DeleteFace114"
delete_face "DeleteFace115"
delete_face "DeleteFace116"
delete_face "DeleteFace117"
delete_face "DeleteFace118"
delete_face "DeleteFace119"
delete_face "DeleteFace120"
delete_face "DeleteFace121"
delete_face "DeleteFace122"
delete_face "DeleteFace123"
delete_face "DeleteFace124"
delete_face "DeleteFace125"
delete_face "DeleteFace126"
delete_face "DeleteFace127"
sketch "Sketch55" plane through (0, 0, 23.1) normal (0, 0, 1) x axis (-1, 0, 0)
  line L1 (-0.9, -53.502) -> (-0.9, -2.4862)
  line L2 (-84.4, -57.002) -> (-4.4, -57.002)
  line L3 (-87.9, -41.9306) -> (-87.9, -53.502)
  line L4 (-89.2, -53.302) -> (-89.2, -41.4294)
  line L5 (-0.4467, -58.302) -> (-84.2, -58.302)
  line L6 (0.1, -7.1762) -> (0.1, -48.812)
  line L7 (-84.2, 2.3138) -> (-0.4467, 2.3138)
  line L8 (-89.2, -14.5589) -> (-89.2, -2.6862)
  line L9 (-87.9, -2.4862) -> (-87.9, -14.0576)
  line L10 (-4.4, 1.0138) -> (-84.4, 1.0138)
  line L11 (1.8892, -53.6758) -> (1.8892, -2.3124)
  arc A1 centre (-4.4, -53.502) radius 3.5 clockwise from (-0.9, -53.502) to (-4.4, -57.002)
  arc A2 centre (-84.4, -53.502) radius 3.5 clockwise from (-84.4, -57.002) to (-87.9, -53.502)
  arc A3 centre (-87.9, -39.9941) radius 1.9365 clockwise from (-87.9, -41.9306) to (-89.2, -41.4294)
  arc A4 centre (-84.2, -53.302) radius 5 clockwise from (-84.2, -58.302) to (-89.2, -53.302)
  arc A5 centre (-4.6, -53.302) radius 6.5 clockwise from (0.1, -48.812) to (-0.4467, -58.302)
  arc A6 centre (-4.6, -2.6862) radius 6.5 clockwise from (-0.4467, 2.3138) to (0.1, -7.1762)
  arc A7 centre (-84.2, -2.6862) radius 5 clockwise from (-89.2, -2.6862) to (-84.2, 2.3138)
  arc A8 centre (-87.9, -15.9941) radius 1.9365 clockwise from (-89.2, -14.5589) to (-87.9, -14.0576)
  arc A9 centre (-84.4, -2.4862) radius 3.5 clockwise from (-87.9, -2.4862) to (-84.4, 1.0138)
  arc A10 centre (-4.4, -2.4862) radius 3.5 clockwise from (-4.4, 1.0138) to (-0.9, -2.4862)
  point P32 (1.8892, -2.3124)
  point P33 (1.8892, -53.6758)
  midpoint A6 P32
  midpoint A5 P33
extrude "Extrude105" add sketch "Sketch55" profile of A5 L6 A6 L11 against normal blind 26.619
fillet "Fillet37" radius 1.5
fillet "Fillet38" radius 1.5
extrude "Extrude106" cut sketch "Sketch54" profile of K4 L7 L8 L9 L10 L11 L13 L14 L15 L16 L17 L18 L19 L20 along normal blind 35 and against normal blind 7
delete_face "DeleteFace128"
fillet "Fillet39" radius 1
fillet "Fillet40" radius 1
fillet "Fillet41" radius 1
extrude "Extrude107" add of existing geometry blind 16.5 second side blind -0.2
extrude "Extrude108" add of existing geometry blind 14.3 (= "13.50 mm + 0.8 mm") second side blind -0.2
sketch "Sketch56" plane through (0, 0, 2.9699) normal (0, 0, -1) x axis (1, 0, 0)
  line L1 (-0.1, -20.1431) -> (-0.1, -33.6431)
  line L2 (-0.8892, -20.1431) -> (-0.1, -20.1431)
  line L3 (-0.8892, -33.6431) -> (-0.8892, -20.1431)
  line L4 (-0.1, -33.6431) -> (-0.8892, -33.6431)
  line L5 (-0.9, -53.3) -> (-0.1, -53.3)
  line L6 (-0.9, -52.3) -> (-0.9, -53.3)
  line L7 (-0.1, -52.3) -> (-0.9, -52.3)
  line L8 (-0.1, -53.3) -> (-0.1, -52.3)
  line L9 (-0.1, -49.8) -> (-0.1, -48.8)
  line L10 (-0.1, -48.8) -> (-0.9, -48.8)
  line L11 (-0.9, -49.8) -> (-0.1, -49.8)
  line L12 (-0.9, -48.8) -> (-0.9, -49.8)
  line L13 (-0.1, -46.3) -> (-0.1, -45.3)
  line L14 (-0.1, -45.3) -> (-0.9, -45.3)
  line L15 (-0.9, -46.3) -> (-0.1, -46.3)
  line L16 (-0.9, -45.3) -> (-0.9, -46.3)
  line L17 (-0.1, -42.8) -> (-0.1, -41.8)
  line L18 (-0.1, -41.8) -> (-0.9, -41.8)
  line L19 (-0.9, -42.8) -> (-0.1, -42.8)
  line L20 (-0.9, -41.8) -> (-0.9, -42.8)
  line L21 (-0.1, -39.3) -> (-0.1, -38.3)
  line L22 (-0.1, -38.3) -> (-0.9, -38.3)
  line L23 (-0.9, -39.3) -> (-0.1, -39.3)
  line L24 (-0.9, -38.3) -> (-0.9, -39.3)
  line L25 (-0.8892, -33.6431) -> (-0.1, -33.6431)
  line L26 (-0.8892, -32.6431) -> (-0.8892, -33.6431)
  line L27 (-0.1, -32.6431) -> (-0.8892, -32.6431)
  line L28 (-0.1, -33.6431) -> (-0.1, -32.6431)
  line L29 (-0.8892, -30.5181) -> (-0.1, -30.5181)
  line L30 (-0.1, -29.5181) -> (-0.8892, -29.5181)
  line L31 (-0.1, -30.5181) -> (-0.8892, -30.5181)
  line L32 (-0.8892, -29.5181) -> (-0.8892, -30.5181)
  line L33 (-0.1, -30.5181) -> (-0.1, -29.5181)
  line L34 (-0.8892, -27.3931) -> (-0.1, -27.3931)
  line L35 (-0.1, -26.3931) -> (-0.8892, -26.3931)
  line L36 (-0.1, -27.3931) -> (-0.8892, -27.3931)
  line L37 (-0.8892, -26.3931) -> (-0.8892, -27.3931)
  line L38 (-0.1, -27.3931) -> (-0.1, -26.3931)
  line L39 (-0.8892, -24.2681) -> (-0.1, -24.2681)
  line L40 (-0.1, -23.2681) -> (-0.8892, -23.2681)
  line L41 (-0.1, -24.2681) -> (-0.8892, -24.2681)
  line L42 (-0.8892, -23.2681) -> (-0.8892, -24.2681)
  line L43 (-0.1, -24.2681) -> (-0.1, -23.2681)
  line L44 (-0.8892, -21.1431) -> (-0.1, -21.1431)
  line L45 (-0.1, -20.1431) -> (-0.8892, -20.1431)
  line L46 (-0.1, -21.1431) -> (-0.8892, -21.1431)
  line L47 (-0.8892, -20.1431) -> (-0.8892, -21.1431)
  line L48 (-0.1, -21.1431) -> (-0.1, -20.1431)
  point P2 (-0.1, -33.6431)
  point P26 (-0.1, -33.6431)
  point P29 (-0.1, -32.6431)
  horizontal L5
  vertical L6
  horizontal L7
  vertical L8
  horizontal L25
  vertical L26
  horizontal L27
  vertical L28
  coincident P2 P26
  dimension "d552" distance P26 P29 = 1
  dimension "d550" R-Pattern1-uDistance = 0
  dimension "d551" R-Pattern1-vDistance = 14
  dimension "d555" R-Pattern2-uDistance = 0
  dimension "d556" R-Pattern2-vDistance = 12.5
sketch "Sketch57" plane through (0, 0, 2.9699) normal (0, 0, -1) x axis (1, 0, 0)
  line L1 (-0.8821, -2.2431) -> (-0.0934, -2.2431)
  line L2 (-0.8892, -15.7431) -> (-0.8892, -3.0301)
  line L3 (-0.1, -15.7431) -> (-0.8892, -15.7431)
  line L4 (-0.1, -2.4862) -> (-0.1, -15.7431)
  line L5 (-0.8892, -15.7431) -> (-0.1, -15.7431)
  line L6 (-0.8892, -14.7431) -> (-0.8892, -15.7431)
  line L7 (-0.1, -14.7431) -> (-0.8892, -14.7431)
  line L8 (-0.1, -15.7431) -> (-0.1, -14.7431)
  line L9 (-0.8892, -12.6181) -> (-0.1, -12.6181)
  line L10 (-0.1, -11.6181) -> (-0.8892, -11.6181)
  line L11 (-0.8892, -11.6181) -> (-0.8892, -12.6181)
  line L12 (-0.1, -12.6181) -> (-0.1, -11.6181)
  line L13 (-0.1, -12.6181) -> (-0.8892, -12.6181)
  line L14 (-0.8892, -9.4931) -> (-0.1, -9.4931)
  line L15 (-0.1, -8.4931) -> (-0.8892, -8.4931)
  line L16 (-0.8892, -8.4931) -> (-0.8892, -9.4931)
  line L17 (-0.1, -9.4931) -> (-0.1, -8.4931)
  line L18 (-0.1, -9.4931) -> (-0.8892, -9.4931)
  line L19 (-0.8892, -6.3681) -> (-0.1, -6.3681)
  line L20 (-0.1, -5.3681) -> (-0.8892, -5.3681)
  line L21 (-0.8892, -5.3681) -> (-0.8892, -6.3681)
  line L22 (-0.1, -6.3681) -> (-0.1, -5.3681)
  line L23 (-0.1, -6.3681) -> (-0.8892, -6.3681)
  line L24 (-0.8892, -3.2431) -> (-0.1, -3.2431)
  line L25 (-0.1, -2.2431) -> (-0.8892, -2.2431)
  line L26 (-0.8892, -2.2431) -> (-0.8892, -3.2431)
  line L27 (-0.1, -3.2431) -> (-0.1, -2.2431)
  line L28 (-0.1, -3.2431) -> (-0.8892, -3.2431)
  arc A1 centre (4.4, -2.4862) radius 4.5 clockwise from (-0.1, -2.4862) to (-0.0934, -2.2431)
  arc A2 centre (4.6, -2.6862) radius 5.5 clockwise from (-0.8892, -3.0301) to (-0.8821, -2.2431)
  point P9 (-0.1, -15.7431)
  point P10 (-0.1, -15.7431)
  point P13 (-0.1, -14.7431)
  horizontal L5
  vertical L6
  horizontal L7
  vertical L8
  coincident P9 P10
  dimension "d557" distance P10 P13 = 1
  dimension "d560" R-Pattern1-uDistance = 0
  dimension "d561" R-Pattern1-vDistance = 12.5
extrude "Extrude109" add sketch "Sketch56" + "Sketch57" profile of S1:L1 S1:L2 S1:L3 S1:L4 S1:L5 S1:L6 S1:L7 S1:L8 S1:L9 S1:L10 S1:L11 S1:L12 S1:L13 S1:L14 S1:L15 S1:L16 S1:L17 S1:L18 S1:L19 S1:L20 S1:L21 S1:L22 S1:L23 S1:L24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 blind 0.5
sphere_primitive "SpherePrimitive2" Diameter 4.8
sphere_primitive "SpherePrimitive3" Diameter 4.8
work_plane "WorkPlane4" AlongDistance -1.5
split "Split2"
move "Move4"
extrude "Extrude119" add of existing geometry blind 5
delete_face "DeleteFace130"
delete_face "DeleteFace131"
delete_face "DeleteFace132"
delete_face "DeleteFace133"
delete_face "DeleteFace134"
delete_face "DeleteFace135"
delete_face "DeleteFace136"
delete_face "DeleteFace137"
